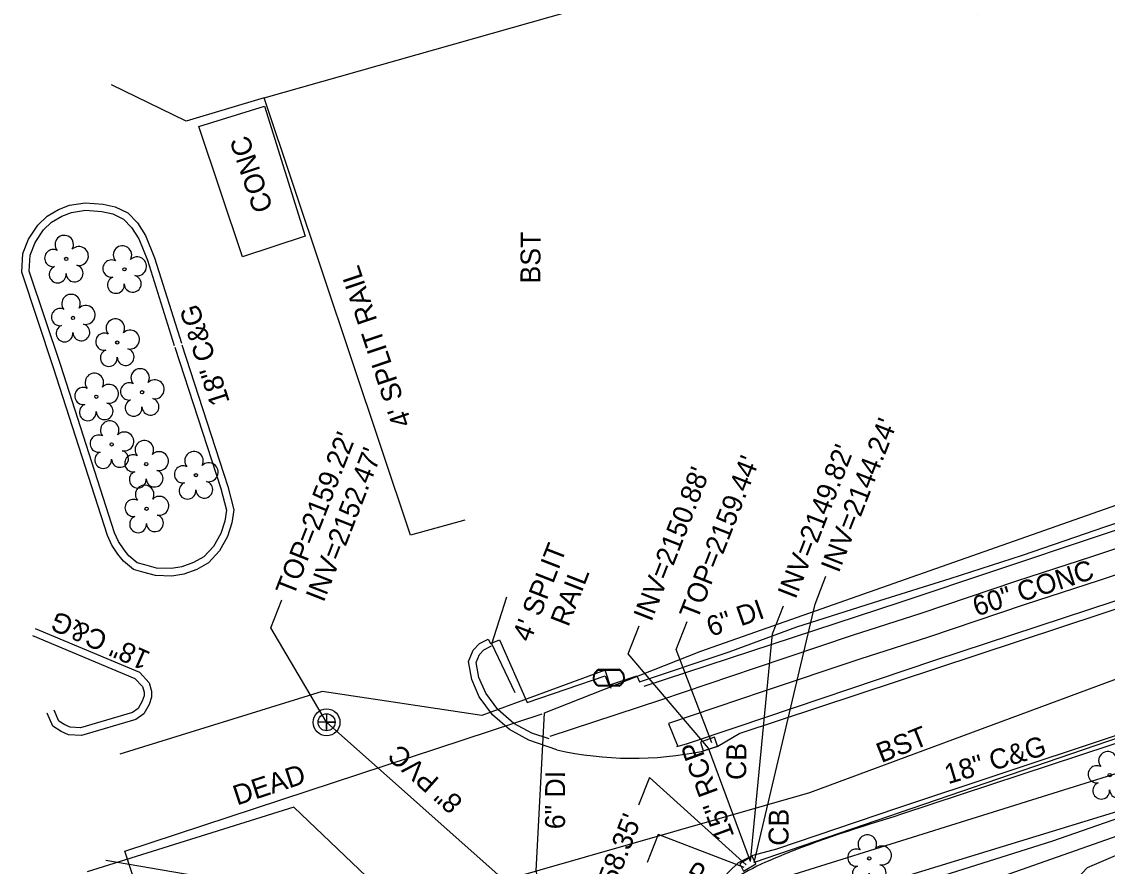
# Model space of a CAD drawing. Extents: x 945964 to 948456, y 631061 to 636061.
# Drawn here: x 946266.7 to 946484.6, y 632699.5 to 632869 of the extents above; entities that cross this region are included whole.
import ezdxf

# ---------------------------------------------------------------- set-up
doc = ezdxf.new("R2010")
doc.units = 0
for name, color, linetype in [('Exist Other Culture Fence Line', 7, 'Continuous'), ('Exist Other Culture Fence Line Text', 7, 'Continuous'), ('Exist Roads Curbs', 7, 'Continuous'), ('Exist Roads Curbs Text', 7, 'Continuous'), ('Exist Roads EOP', 7, 'Continuous'), ('Exist Roads EOP Other', 7, 'Continuous'), ('Exist Roads EOP Other Text', 7, 'Continuous'), ('Exist Structure Minor Catch Basin', 7, 'Continuous'), ('Exist Structure Minor Catch Basin Text', 7, 'Continuous'), ('Exist Structure Minor Catch Basin Top Elevation', 7, 'Continuous'), ('Exist Structure Minor Pipes RCP 15 Inch', 7, 'Continuous'), ('Exist Structure Minor Pipes RCP 15 Inch Invert', 7, 'Continuous'), ('Exist Structure Minor Pipes RCP 15 Inch Text', 7, 'Continuous'), ('Exist Structure Minor Pipes RCP 18 Inch', 7, 'Continuous'), ('Exist Structure Minor Pipes RCP 18 Inch Invert', 7, 'Continuous'), ('Exist Structure Minor Pipes RCP 18 Inch Text', 7, 'Continuous'), ('Exist Utilities Gas UG Line SUE', 7, 'Continuous'), ('Exist Utilities Power UG Cable SUE', 7, 'Continuous'), ('Exist Utilities Sanitary Sewer Manhole CELL', 7, 'Continuous'), ('Exist Utilities Sanitary Sewer Manhole Top Elevation', 7, 'Continuous'), ('Exist Utilities Sanitary Sewer UG Line', 7, 'Continuous'), ('Exist Utilities Sanitary Sewer UG Line Text', 7, 'Continuous'), ('Exist Utilities Telephone UG Cable SUE', 7, 'Continuous'), ('Exist Utilities Telephone UG FO SUE', 7, 'Continuous'), ('Exist Utilities Water Meter CELL', 7, 'Continuous'), ('Exist Utilities Water UG Line SUE', 7, 'Continuous'), ('Exist Utilities Water UG Line SUE Text', 7, 'Continuous'), ('Exist Vegetation Hedge Row', 7, 'Continuous'), ('Exist Vegetation Tree CELL', 7, 'Continuous')]:
    doc.layers.add(name, color=color, linetype=linetype)

# ---------------------------------------------------------------- blocks, each defined once
blk = doc.blocks.new('EXIST UTILITIES WATER METER')
at = {"layer": 'Exist Utilities Water Meter CELL'}
blk.add_line((0, 0), (0, 0), dxfattribs=at)
for points in [[(-0.0408, 0.034), (0.0408, 0.034)], [(-0.0408, 0.0312), (0.0408, 0.0312)], [(0.0408, -0.0312), (-0.0413, -0.0312)], [(0.0408, -0.034), (-0.0413, -0.034)]]:
    blk.add_lwpolyline(points, dxfattribs=at)
for centre, radius, start, end in [((-0.0261, -0.0001), 0.0371, 113.178, 245.9794), ((-0.0259, -0.0001), 0.0347, 115.3009, 243.7824), ((0.0259, 0), 0.0371, 293.6483, 66.3084), ((0.0261, 0), 0.0345, 295.1272, 64.8728)]:
    blk.add_arc(centre, radius, start, end, dxfattribs=at)
blk = doc.blocks.new('EXIST UTILITIES SANITARY SEWER MANHOLE')
at = {"layer": 'Exist Utilities Sanitary Sewer Manhole CELL'}
blk.add_lwpolyline([(0, 0.0342), (0, -0.0342), (0, 0), (0.0342, 0), (-0.0342, 0)], dxfattribs=at)
for radius in [0.0539, 0.0342]:
    blk.add_circle((0, 0), radius, dxfattribs=at)
blk = doc.blocks.new('EXIST VEGETATION TREE')
at = {"layer": 'Exist Vegetation Tree CELL'}
blk.add_line((0, 0), (0, 0), dxfattribs=at)
blk.add_circle((0, 0), 0.00652, dxfattribs=at)
for centre, radius, start, end in [((-0.0077, 0.0575), 0.0371, 330.1651, 219.7134), ((0.051, 0.0118), 0.038, 257.1011, 134.1999), ((-0.0521, 0.0031), 0.0345, 62.6636, 279.3457), ((-0.0341, -0.0624), 0.0338, 111.5671, 6.231), ((0.0335, -0.058), 0.034, 181.2822, 74.56)]:
    blk.add_arc(centre, radius, start, end, dxfattribs=at)

msp = doc.modelspace()

# ---------------------------------------------------------------- linework, layer by layer
at = {"layer": 'Exist Other Culture Fence Line'}
for points in [[(946355.67, 632768.98), (946344.74, 632765.98), (946315.38, 632853.69), (946391.91, 632875.45), (946410.69, 632881.47), (946458.52, 632870.61), (946462.21, 632871.66), (946456.11, 632887.58)], [(946315.38, 632853.69), (946299.74, 632849.02), (946284.75, 632856.34)], [(946542.28, 632785.83), (946501.77, 632772.1), (946442.96, 632752.47), (946391.56, 632735.6)], [(946365.77, 632734.32), (946361.07, 632744.13), (946364.06, 632753.59)]]:
    msp.add_lwpolyline(points, dxfattribs=at)
at = {"layer": 'Exist Roads Curbs'}
for points in [[(946297.46, 632803.7), (946306.66, 632775.31), (946307.8, 632770.94), (946307.46, 632768.75), (946306.66, 632766.29), (946305.21, 632763.7), (946303.26, 632761.61), (946301.21, 632760.45), (946298.88, 632759.58), (946296.76, 632759.26), (946293.77, 632759.35), (946291.45, 632759.99), (946289.89, 632760.4), (946288.2, 632761.79), (946287.26, 632762.99), (946286.13, 632764.69), (946285.36, 632766.41), (946274.55, 632799.98), (946268.23, 632818.91), (946268.41, 632822.13), (946269.44, 632824.66), (946271.1, 632827.19), (946272.73, 632828.77), (946274.78, 632829.95), (946276.71, 632830.72), (946279.51, 632831.14), (946282.81, 632830.89), (946284.99, 632830.4), (946287.12, 632829.37), (946288.75, 632827.69), (946290.21, 632825.39), (946291.95, 632821.11), (946297.33, 632804)], [(946491.19, 632754.39), (946449.9, 632740.8), (946410.24, 632727.44), (946400.09, 632724.02), (946398.12, 632723.45)], [(946268.86, 632745.84), (946289.45, 632737.21), (946290.96, 632735.57), (946291.28, 632734.45), (946291.28, 632733.71), (946290.91, 632732.61), (946290.06, 632731.14), (946288.98, 632730.34), (946278.54, 632727.27), (946276.46, 632727.39), (946275.38, 632727.89), (946274.15, 632728.64), (946273.23, 632730.81)], [(946372.58, 632725.05), (946369.08, 632726.2), (946365.5, 632728.18), (946362.31, 632730.95), (946359.86, 632734.26), (946358.49, 632737.4), (946357.95, 632740.41), (946358.61, 632742.03), (946359.5, 632742.97), (946361.04, 632743.75)], [(946527.29, 632737.67), (946485.1, 632723.73), (946443.29, 632709.94)]]:
    msp.add_lwpolyline(points, dxfattribs=at)
for points in [[(946601.93, 632772.67), (946579.15, 632743.42), (946547.53, 632710.06), (946519.46, 632682.69), (946496.47, 632656.95), (946474.49, 632624.89), (946453.03, 632584.16), (946438.45, 632541.43), (946430.15, 632490.73), (946428.83, 632457.38), (946430.2, 632433.68), (946432.57, 632412.52), (946425.74, 632395.61), (946417.04, 632384.69)], [(946443.29, 632709.94), (946418.6, 632701.43), (946405.91, 632693.72), (946402.27, 632688.72), (946400.06, 632684.45), (946398.16, 632678.07), (946398.29, 632672.08), (946400.56, 632662.72), (946404.62, 632636.22), (946402.97, 632621.07), (946384.84, 632587.17), (946377.39, 632579.37), (946368.81, 632574.06)]]:
    msp.add_spline(points, degree=3, dxfattribs=at)
at = {"layer": 'Exist Roads EOP'}
for points in [[(946298.88, 632804.16), (946308.1, 632775.73), (946309.32, 632771.02), (946308.92, 632768.4), (946308.04, 632765.68), (946306.43, 632762.81), (946304.19, 632760.41), (946301.84, 632759.09), (946299.26, 632758.12), (946296.85, 632757.75), (946293.55, 632757.86), (946291.06, 632758.54), (946289.19, 632759.03), (946287.12, 632760.74), (946286.04, 632762.12), (946284.82, 632763.96), (946283.96, 632765.87), (946273.12, 632799.51), (946266.72, 632818.7), (946266.93, 632822.46), (946268.1, 632825.36), (946269.94, 632828.15), (946271.82, 632829.98), (946274.13, 632831.31), (946276.31, 632832.17), (946279.45, 632832.65), (946283.04, 632832.38), (946285.49, 632831.83), (946288.01, 632830.61), (946289.94, 632828.63), (946291.55, 632826.07), (946293.36, 632821.62), (946298.76, 632804.45)], [(946360.36, 632745.09), (946360.81, 632744.2), (946362.58, 632744.95), (946368.15, 632732.35), (946383.83, 632737.73), (946384.56, 632735.86), (946390.18, 632737.73), (946390.68, 632736.52), (946408.72, 632742.55), (946422.32, 632747.58), (946438.92, 632752.86), (946453.03, 632757.25), (946467.57, 632761.91), (946484.29, 632767.7), (946501.66, 632773.54), (946503.34, 632774.16), (946503.05, 632774.92), (946511.76, 632778.07)], [(946541.03, 632769.28), (946536.78, 632766.76), (946533.82, 632765.92), (946528.8, 632765.25), (946491.79, 632752.89), (946450.33, 632739.22), (946410.88, 632726.15), (946406.42, 632723.56), (946403.47, 632722.63)], [(946269.44, 632747.22), (946290.34, 632738.47), (946292.31, 632736.33), (946292.78, 632734.67), (946292.79, 632733.47), (946292.29, 632731.99), (946291.2, 632730.12), (946289.65, 632728.98), (946278.71, 632725.76), (946276.09, 632725.91), (946274.67, 632726.56), (946272.95, 632727.6), (946271.85, 632730.23)], [(946550.72, 632747.33), (946538.92, 632743.34), (946534.18, 632742.6), (946531.1, 632741.53), (946526.64, 632739.08), (946484.59, 632725.12), (946442.49, 632711.17), (946418.22, 632702.92), (946413.45, 632701.7), (946410.52, 632700.21), (946407.04, 632696.87)], [(946374.1, 632722.86), (946368.48, 632724.82), (946364.63, 632726.94), (946361.2, 632729.92), (946358.55, 632733.5), (946357.05, 632736.96), (946356.4, 632740.57), (946357.33, 632742.86), (946358.59, 632744.19), (946360.36, 632745.09)]]:
    msp.add_lwpolyline(points, dxfattribs=at)
msp.add_ellipse((946389.31, 632791.38), major_axis=(69.77, -7.95), ratio=0.999521, start_param=4.607459, end_param=5.028751, dxfattribs=at)
msp.add_spline([(946603.2, 632771.71), (946580.04, 632742.14), (946547.72, 632708.15), (946520.62, 632681.67), (946497.88, 632656.28), (946475.52, 632623.93), (946454.54, 632583.75), (946439.95, 632540.86), (946431.6, 632490.76), (946430.35, 632457.42), (946431.68, 632434.16), (946433.99, 632412.2), (946427.3, 632395.46), (946417.68, 632383.18)], degree=3, dxfattribs=at)
at = {"layer": 'Exist Roads EOP Other'}
for points in [[(946302.26, 632847.96), (946315.44, 632852.02), (946323.64, 632825.94)], [(946323.64, 632825.94), (946311.04, 632821.81), (946302.26, 632847.96)], [(946497.91, 632767.09), (946481.4, 632761.6), (946466.37, 632756.75), (946447.15, 632750.23), (946433.37, 632745.84), (946413.9, 632739.29), (946394.92, 632732.86)], [(946499.51, 632762.35), (946482.96, 632756.84), (946467.94, 632752), (946448.71, 632745.48), (946434.93, 632741.08), (946415.5, 632734.55), (946396.53, 632728.13)], [(946394.92, 632732.86), (946372.74, 632725.57)], [(946396.53, 632728.13), (946398.43, 632723.54)]]:
    msp.add_lwpolyline(points, dxfattribs=at)
at = {"layer": 'Exist Structure Minor Catch Basin'}
for points in [[(946402.94, 632724.44), (946403.49, 632722.7), (946406.37, 632723.64), (946405.76, 632725.4), (946402.94, 632724.44)], [(946413.33, 632701.52), (946410.83, 632700.01), (946411.57, 632698.55), (946414.09, 632699.99), (946413.33, 632701.52)]]:
    msp.add_lwpolyline(points, dxfattribs=at)
at = {"layer": 'Exist Structure Minor Catch Basin Top Elevation'}
for points in [[(946405.2, 632724.3), (946398.09, 632743.01), (946400.28, 632748.6)], [(946412.13, 632699.77), (946392.69, 632717.33), (946390.5, 632711.75)]]:
    msp.add_lwpolyline(points, dxfattribs=at)
at = {"layer": 'Exist Structure Minor Pipes RCP 15 Inch'}
msp.add_line((946413, 632700.48), (946404.59, 632723.21), dxfattribs=at)
at = {"layer": 'Exist Structure Minor Pipes RCP 15 Inch Invert'}
for points in [[(946413, 632700.48), (946417.43, 632746.18), (946419.62, 632751.77)], [(946404.59, 632723.21), (946388.44, 632742.15), (946390.63, 632747.73)]]:
    msp.add_lwpolyline(points, dxfattribs=at)
at = {"layer": 'Exist Structure Minor Pipes RCP 18 Inch'}
msp.add_line((946531.9, 632740.69), (946413.73, 632700.3), dxfattribs=at)
at = {"layer": 'Exist Structure Minor Pipes RCP 18 Inch Invert'}
for points in [[(946413.73, 632700.3), (946425.95, 632752.11), (946428.14, 632757.69)], [(946411.74, 632699.25), (946394.45, 632705.86), (946392.27, 632700.27)]]:
    msp.add_lwpolyline(points, dxfattribs=at)
at = {"layer": 'Exist Utilities Gas UG Line SUE'}
for points in [[(946328.8, 632353.04), (946373.09, 632367.86), (946390.79, 632374.2), (946416.26, 632409.78), (946398.86, 632469.97), (946389.31, 632500.41), (946363.99, 632571.54), (946360.18, 632599.46), (946347.82, 632660.28), (946348.31, 632668.93), (946363.39, 632670.11), (946405.63, 632685.78), (946486.74, 632710.56), (946558.09, 632746.02), (946590.61, 632771.11), (946619.22, 632810.2), (946619.67, 632824.44), (946594.97, 632905.61)], [(946363.43, 632670.45), (946360.96, 632677.62), (946352, 632682.12), (946321.31, 632711.34), (946279.89, 632698.37)]]:
    msp.add_lwpolyline(points, dxfattribs=at)
at = {"layer": 'Exist Utilities Power UG Cable SUE'}
for points in [[(946360.13, 632660.61), (946366.34, 632669.16), (946406.95, 632683.52), (946473.64, 632704.64), (946529.01, 632723.91), (946572.73, 632752.79), (946602.05, 632778.83), (946632.04, 632830.29), (946638.92, 632863.65), (946639.32, 632905.11), (946627.59, 632976.28), (946631.01, 632982.04)], [(946358.83, 632671.87), (946409.81, 632694.19), (946491.07, 632719.59), (946512.34, 632726.76), (946527.94, 632732.44), (946563.12, 632750.98), (946591.54, 632775.57), (946597.73, 632780.43), (946610.71, 632793.64), (946619, 632807.83), (946625.48, 632824.38), (946631.48, 632842.49), (946635.14, 632865.8), (946629.47, 632896.55)]]:
    msp.add_lwpolyline(points, dxfattribs=at)
at = {"layer": 'Exist Utilities Sanitary Sewer Manhole Top Elevation'}
msp.add_lwpolyline([(946327.9, 632728.4), (946316.71, 632747.37), (946318.9, 632752.96)], dxfattribs=at)
at = {"layer": 'Exist Utilities Sanitary Sewer UG Line'}
msp.add_lwpolyline([(946402.92, 632479.56), (946384.25, 632544.62), (946420.33, 632646.2), (946327.9, 632728.4)], dxfattribs=at)
at = {"layer": 'Exist Utilities Telephone UG Cable SUE'}
msp.add_lwpolyline([(946359.71, 632661.63), (946399.78, 632679.58), (946438.25, 632688.61), (946513.39, 632715.06), (946554.62, 632735.94), (946609.33, 632779.21), (946641.07, 632799.75), (946626.79, 632844.16), (946603.53, 632869.47), (946569.01, 632976.01), (946560.85, 632993.4), (946550.79, 632988.99)], dxfattribs=at)
at = {"layer": 'Exist Utilities Telephone UG FO SUE'}
msp.add_line((946283.62, 632700.75), (946340.89, 632690.95), dxfattribs=at)
msp.add_lwpolyline([(946343.46, 632690.97), (946424.89, 632714.31), (946503.77, 632743.56), (946582.19, 632771.71)], dxfattribs=at)
at = {"layer": 'Exist Utilities Water UG Line SUE'}
for p, q in [((946287.4, 632702.51), (946371.18, 632730.08)), ((946339.62, 632546.22), (946287.4, 632702.51))]:
    msp.add_line(p, q, dxfattribs=at)
for points in [[(946450.51, 632206.48), (946434.39, 632257.32), (946406.99, 632342.82), (946396.29, 632375.97), (946378.9, 632423.81), (946365.5, 632463.34), (946339.7, 632545.71), (946360.27, 632568.18), (946378.23, 632596.81), (946392.83, 632624.5), (946375.23, 632673.95), (946369.96, 632698.61), (946371.67, 632730.29), (946403.03, 632742.7), (946539.78, 632790.77), (946609.96, 632816.5), (946596.43, 632867.38), (946587.53, 632902.31), (946563.28, 632978.1), (946529.52, 633075.74), (946498.27, 633161.68), (946472.52, 633239.25)], [(946385.03, 632735.21), (946383.79, 632738.89), (946359.05, 632729.78), (946327.02, 632734.58), (946286.44, 632721.99)]]:
    msp.add_lwpolyline(points, dxfattribs=at)
at = {"layer": 'Exist Vegetation Hedge Row'}
msp.add_lwpolyline([(946508.23, 632698.85), (946469.4, 632644.26), (946468.63, 632632.76), (946453.01, 632608.66), (946438.09, 632591.02), (946431.9, 632578.64), (946431.93, 632555.16), (946425.49, 632540.17), (946414.91, 632544.82), (946407.52, 632561.16), (946424.07, 632594.79), (946450.38, 632643.82), (946460.27, 632667.16), (946469.78, 632687.73), (946480.6, 632699.26), (946493.29, 632704.68), (946502.78, 632708.02), (946508.13, 632698.23)], dxfattribs=at)

# ---------------------------------------------------------------- block references
at = {"layer": 'Exist Utilities Sanitary Sewer Manhole CELL', "xscale": 50, "yscale": 50}
msp.add_blockref('EXIST UTILITIES SANITARY SEWER MANHOLE', (946327.9, 632728.4), dxfattribs=at)
at = {"layer": 'Exist Utilities Water Meter CELL', "xscale": 50, "yscale": 50}
msp.add_blockref('EXIST UTILITIES WATER METER', (946384.56, 632737.33), dxfattribs=at)
at = {"layer": 'Exist Vegetation Tree CELL', "xscale": 50, "yscale": 50}
for p in [(946275.65, 632821.38), (946287.33, 632819.29), (946277.01, 632809.55), (946285.9, 632804.61), (946281.69, 632793.72), (946290.88, 632794.63), (946284.77, 632784.16), (946291.72, 632780.21), (946301.69, 632777.99), (946291.78, 632771.25), (946485.09, 632717.81), (946436.82, 632701.09)]:
    msp.add_blockref('EXIST VEGETATION TREE', p, dxfattribs=at)

# ---------------------------------------------------------------- texts
at = {"layer": 'Exist Other Culture Fence Line Text'}
for s, rotation, p in [("4' SPLIT RAIL", 108.504, (946345.05, 632788.35)), ("4' SPLIT", 68.7162, (946368.78, 632744.31)), ('RAIL', 68.7162, (946376.42, 632747.39))]:
    msp.add_text(s, height=4, rotation=rotation, dxfattribs=at).set_placement(p)
at = {"layer": 'Exist Roads Curbs Text'}
for rotation, p in [(107.8542, (946308.52, 632792.69)), (156.1042, (946292.8, 632742.36)), (16.7601, (946452.65, 632715.95))]:
    msp.add_text('18" C&G', height=4, rotation=rotation, dxfattribs=at).set_placement(p)
at = {"layer": 'Exist Roads EOP Other Text'}
for s, rotation, p in [('CONC', 108.5856, (946317.21, 632831.5)), ('BST', 89.5187, (946370.79, 632816.43)), ('60" CONC', 17.8648, (946458.37, 632749.62)), ('BST', 21.8035, (946439.26, 632720.2))]:
    msp.add_text(s, height=4, rotation=rotation, dxfattribs=at).set_placement(p)
at = {"layer": 'Exist Structure Minor Catch Basin Text'}
for p in [(946412.11, 632716.81), (946420.6, 632703.61)]:
    msp.add_text('CB', height=4, rotation=89.5187, dxfattribs=at).set_placement(p)
at = {"layer": 'Exist Structure Minor Catch Basin Top Elevation'}
for s, p in [("TOP=2159.44'", (946402.3, 632748.76)), ("TOP=2158.35'", (946378.66, 632676.91))]:
    msp.add_text(s, height=4, rotation=68.6189, dxfattribs=at).set_placement(p)
at = {"layer": 'Exist Structure Minor Pipes RCP 15 Inch Invert'}
for s, p in [("INV=2149.82'", (946422.02, 632752.94)), ("INV=2150.88'", (946393.09, 632748.42))]:
    msp.add_text(s, height=4, rotation=68.6189, dxfattribs=at).set_placement(p)
at = {"layer": 'Exist Structure Minor Pipes RCP 15 Inch Text'}
msp.add_text('15" RCP', height=4, rotation=110.3158, dxfattribs=at).set_placement((946409.79, 632705.6))
at = {"layer": 'Exist Structure Minor Pipes RCP 18 Inch Invert'}
msp.add_text("INV=2144.24'", height=4, rotation=68.6189, dxfattribs=at).set_placement((946430.69, 632758.21))
at = {"layer": 'Exist Structure Minor Pipes RCP 18 Inch Text'}
msp.add_text('18" RCP', height=4, rotation=59.1616, dxfattribs=at).set_placement((946395.07, 632681.16))
at = {"layer": 'Exist Utilities Sanitary Sewer Manhole Top Elevation'}
for s, p in [("TOP=2159.22'", (946321.28, 632753.51)), ("INV=2152.47'", (946327.32, 632752.31))]:
    msp.add_text(s, height=4, rotation=68.6189, dxfattribs=at).set_placement(p)
at = {"layer": 'Exist Utilities Sanitary Sewer UG Line Text'}
msp.add_text('8" PVC', height=4, rotation=138.3531, dxfattribs=at).set_placement((946355.49, 632712.7))
at = {"layer": 'Exist Utilities Water UG Line SUE Text'}
for s, rotation, p in [('6" DI', 19.3688, (946405.03, 632745.52)), ('DEAD', 18.217, (946309.93, 632711.69)), ('6" DI', 89.8847, (946375.76, 632706.94))]:
    msp.add_text(s, height=4, rotation=rotation, dxfattribs=at).set_placement(p)

doc.saveas('drawing.dxf')
